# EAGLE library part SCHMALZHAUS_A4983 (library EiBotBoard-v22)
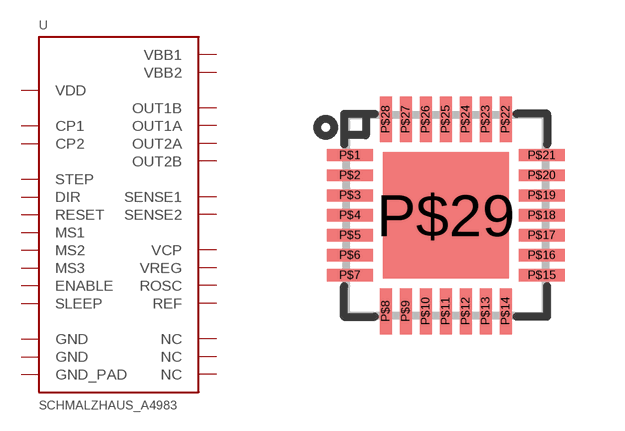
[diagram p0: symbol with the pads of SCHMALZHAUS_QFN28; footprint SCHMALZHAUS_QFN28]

Designator prefix -

## SCHMALZHAUS_A4983  [SCHMALZHAUS_QFN28]
P$1  OUT2B
P$2  ENABLE  in
P$3  GND  pwr
P$4  CP1
P$5  CP2
P$6  VCP
P$7  NC  nc
P$8  VREG
P$9  MS1  in
P$10  MS2  in
P$11  MS3  in
P$12  RESET  in
P$13  ROSC
P$14  SLEEP  in
P$15  VDD  pwr
P$16  STEP  in
P$17  REF
P$18  GND  pwr
P$19  DIR  in
P$20  NC  nc
P$21  OUT1B
P$22  VBB1
P$23  SENSE1
P$24  OUT1A
P$25  NC  nc
P$26  OUT2A
P$27  SENSE2
P$28  VBB2
P$29  GND_PAD  pwr

## Footprint SCHMALZHAUS_QFN28 (pad centres in mm)
smd 1.15 x 0.3: P$1 -2.4,1.5; P$2 -2.4,1; P$3 -2.4,0.5; P$4 -2.4,0; P$5 -2.4,-0.5; P$6 -2.4,-1; P$7 -2.4,-1.5; P$15 2.4,-1.5; P$16 2.4,-1; P$17 2.4,-0.5; P$18 2.4,0; P$19 2.4,0.5; P$20 2.4,1; P$21 2.4,1.5
smd 0.3 x 1.15: P$8 -1.5,-2.4; P$9 -1,-2.4; P$10 -0.5,-2.4; P$11 0,-2.4; P$12 0.5,-2.4; P$13 1,-2.4; P$14 1.5,-2.4; P$22 1.5,2.4; P$23 1,2.4; P$24 0.5,2.4; P$25 0,2.4; P$26 -0.5,2.4; P$27 -1,2.4; P$28 -1.5,2.4
smd 3.15 x 3.15: P$29 0,0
